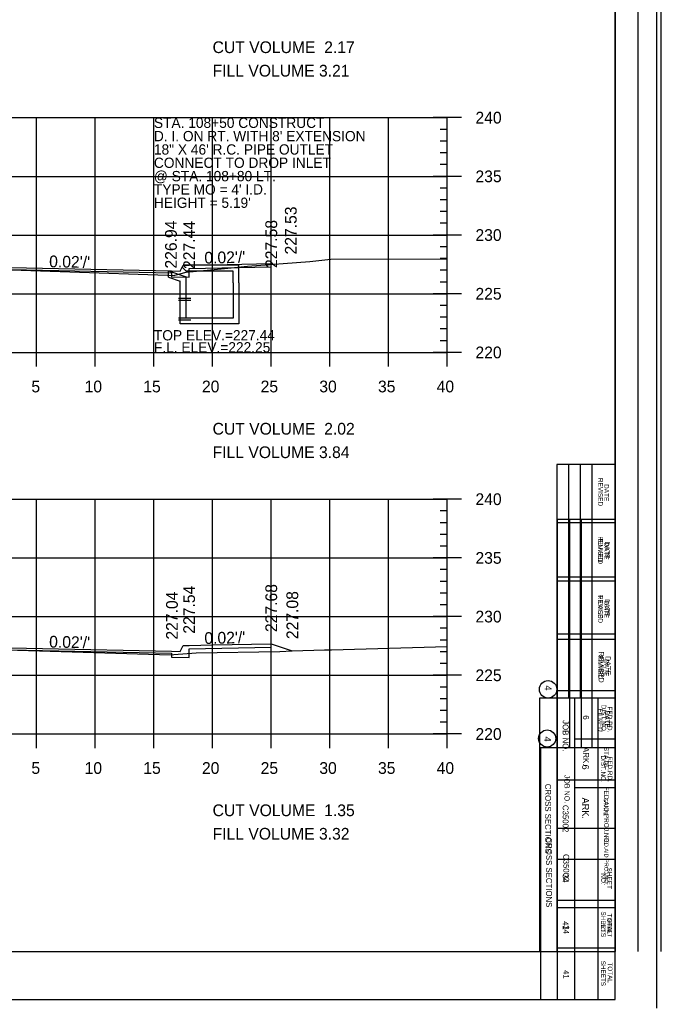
# Model space of a CAD drawing. Extents: x 1367903 to 1373764, y 376865 to 382130.
# Drawn here: x 1371989.4 to 1372098.7, y 377279.1 to 377447.5 of the extents above; entities that cross this region are included whole.
import ezdxf

# ---------------------------------------------------------------- set-up
doc = ezdxf.new("R2010")
doc.units = 0
for name, color, linetype in [('R_Axis', 7, 'Continuous'), ('R_Axis Annot', 7, 'Continuous'), ('R_Border', 7, 'Continuous'), ('R_Border Notes', 7, 'Continuous'), ('R_Border PE', 7, 'Continuous'), ('R_Draft', 7, 'Continuous'), ('R_Exist Surface', 7, 'Continuous'), ('R_Fin Surface', 7, 'Continuous'), ('R_Fin Surface Annot', 7, 'Continuous'), ('R_Grid', 7, 'Continuous'), ('R_Water', 7, 'Continuous'), ('R_Water Annot', 7, 'Continuous')]:
    doc.layers.add(name, color=color, linetype=linetype)

msp = doc.modelspace()

# ---------------------------------------------------------------- linework, layer by layer
for p, q in [((1372017.11, 377405.38), (1372017.28, 377405.71)), ((1372026.78, 377405.71), (1372017.28, 377405.71)), ((1372026.78, 377402.71), (1372026.78, 377405.71)), ((1372014.78, 377404.75), (1372017.78, 377403.71)), ((1372017.11, 377405.38), (1372017.78, 377404.71)), ((1372025.78, 377404.71), (1372017.78, 377404.71)), ((1372025.78, 377402.71), (1372025.78, 377404.71)), ((1372014.78, 377403.69), (1372016.78, 377403)), ((1372016.78, 377402.71), (1372016.78, 377403)), ((1372017.78, 377402.71), (1372017.78, 377403.71))]:
    msp.add_line(p, q)
for points in [[(1371946.28, 377405.71), (1371946.28, 377405.05), (1371946.28, 377405.05), (1371946.28, 377403.68), (1371949.28, 377403.74), (1371949.28, 377404.41), (1371982.28, 377405.07), (1372015.28, 377404.41), (1372015.28, 377403.74), (1372018.28, 377403.68), (1372018.28, 377405.13), (1372032.28, 377405.41), (1372032.28, 377405.99)], [(1372014.78, 377403.69), (1372014.78, 377404.75)], [(1371946.28, 377340.92), (1371946.28, 377340.25), (1371946.28, 377340.25), (1371946.28, 377338.89), (1371949.28, 377338.95), (1371949.28, 377339.62), (1371982.28, 377340.28), (1372015.28, 377339.62), (1372015.28, 377338.95), (1372018.28, 377338.89), (1372018.28, 377340.33), (1372032.28, 377340.61), (1372032.28, 377341.2)]]:
    msp.add_lwpolyline(points)
at = {"layer": 'R_Axis'}
for p, q in [((1372064.68, 377430.84), (1372059.88, 377430.84)), ((1372062.28, 377390.84), (1372062.28, 377430.84)), ((1372062.28, 377428.84), (1372061.08, 377428.84)), ((1372062.28, 377426.84), (1372061.08, 377426.84)), ((1372062.28, 377424.84), (1372061.08, 377424.84)), ((1372062.28, 377422.84), (1372061.08, 377422.84)), ((1372064.68, 377420.84), (1372059.88, 377420.84)), ((1372062.28, 377418.84), (1372061.08, 377418.84)), ((1372062.28, 377416.84), (1372061.08, 377416.84)), ((1372062.28, 377414.84), (1372061.08, 377414.84)), ((1372062.28, 377412.84), (1372061.08, 377412.84)), ((1372064.68, 377410.84), (1372059.88, 377410.84)), ((1372062.28, 377408.84), (1372061.08, 377408.84)), ((1372062.28, 377406.84), (1372061.08, 377406.84)), ((1372062.28, 377404.84), (1372061.08, 377404.84)), ((1372062.28, 377402.84), (1372061.08, 377402.84)), ((1372064.68, 377400.84), (1372059.88, 377400.84)), ((1372062.28, 377398.84), (1372061.08, 377398.84)), ((1372062.28, 377396.84), (1372061.08, 377396.84)), ((1372062.28, 377394.84), (1372061.08, 377394.84)), ((1371992.28, 377388.44), (1371992.28, 377393.24)), ((1372002.28, 377388.44), (1372002.28, 377393.24)), ((1372012.28, 377388.44), (1372012.28, 377393.24)), ((1372022.28, 377388.44), (1372022.28, 377393.24)), ((1372032.28, 377388.44), (1372032.28, 377393.24)), ((1372042.28, 377388.44), (1372042.28, 377393.24)), ((1372052.28, 377388.44), (1372052.28, 377393.24)), ((1372062.28, 377392.84), (1372061.08, 377392.84)), ((1372062.28, 377388.44), (1372062.28, 377393.24)), ((1371902.28, 377390.84), (1372062.28, 377390.84)), ((1372064.68, 377390.84), (1372059.88, 377390.84)), ((1372064.68, 377365.84), (1372059.88, 377365.84)), ((1372062.28, 377325.84), (1372062.28, 377365.84)), ((1372062.28, 377363.84), (1372061.08, 377363.84)), ((1372062.28, 377361.84), (1372061.08, 377361.84)), ((1372062.28, 377359.84), (1372061.08, 377359.84)), ((1372062.28, 377357.84), (1372061.08, 377357.84)), ((1372064.68, 377355.84), (1372059.88, 377355.84)), ((1372062.28, 377353.84), (1372061.08, 377353.84)), ((1372062.28, 377351.84), (1372061.08, 377351.84)), ((1372062.28, 377349.84), (1372061.08, 377349.84)), ((1372062.28, 377347.84), (1372061.08, 377347.84)), ((1372064.68, 377345.84), (1372059.88, 377345.84)), ((1372062.28, 377343.84), (1372061.08, 377343.84)), ((1372062.28, 377341.84), (1372061.08, 377341.84)), ((1372062.28, 377339.84), (1372061.08, 377339.84)), ((1372062.28, 377337.84), (1372061.08, 377337.84)), ((1372064.68, 377335.84), (1372059.88, 377335.84)), ((1372062.28, 377333.84), (1372061.08, 377333.84)), ((1372062.28, 377331.84), (1372061.08, 377331.84)), ((1372062.28, 377329.84), (1372061.08, 377329.84)), ((1371992.28, 377323.44), (1371992.28, 377328.24)), ((1372002.28, 377323.44), (1372002.28, 377328.24)), ((1372012.28, 377323.44), (1372012.28, 377328.24)), ((1372022.28, 377323.44), (1372022.28, 377328.24)), ((1372032.28, 377323.44), (1372032.28, 377328.24)), ((1372042.28, 377323.44), (1372042.28, 377328.24)), ((1372052.28, 377323.44), (1372052.28, 377328.24)), ((1372062.28, 377323.44), (1372062.28, 377328.24)), ((1372062.28, 377327.84), (1372061.08, 377327.84)), ((1371902.28, 377325.84), (1372062.28, 377325.84)), ((1372064.68, 377325.84), (1372059.88, 377325.84))]:
    msp.add_line(p, q, dxfattribs=at)
at = {"layer": 'R_Border'}
for p, q in [((1372097.94, 377620.35), (1372097.94, 377279.12)), ((1372090.9, 377280.59), (1372090.9, 377611.47)), ((1372090.9, 377446.03), (1372090.9, 377446.03)), ((1372081.09, 377280.59), (1372081.09, 377362.43)), ((1372081.09, 377362.43), (1372090.9, 377362.43)), ((1372081.09, 377362.43), (1372083.13, 377362.43)), ((1372083.13, 377362.43), (1372083.13, 377323.46)), ((1372085.07, 377362.43), (1372085.07, 377323.46)), ((1372086.92, 377362.43), (1372086.92, 377323.46)), ((1372081.09, 377352.62), (1372090.71, 377352.62)), ((1372081.09, 377342.9), (1372090.71, 377342.9)), ((1372081.09, 377333.27), (1372090.71, 377333.27)), ((1372090.9, 377323.46), (1372078.17, 377323.46)), ((1372078.17, 377323.46), (1372078.17, 377280.59)), ((1372084.01, 377280.59), (1372084.01, 377323.46)), ((1372087.99, 377280.59), (1372087.99, 377323.46)), ((1372090.9, 377316.65), (1372084.01, 377316.65)), ((1372090.9, 377309.75), (1372081.09, 377309.75)), ((1372090.9, 377296.24), (1372081.09, 377296.24)), ((1372090.9, 377289.33), (1372081.09, 377289.33)), ((1371886.58, 377280.59), (1372090.9, 377280.59))]:
    msp.add_line(p, q, dxfattribs=at)
msp.add_circle((1372079.31, 377325.07), 1.46, dxfattribs=at)
at = {"layer": 'R_Border PE'}
for p, q in [((1372094.83, 377288.8), (1372094.83, 377610.76)), ((1372098.74, 377288.8), (1372098.74, 377610.76)), ((1372090.9, 377603.25), (1372090.9, 377288.8)), ((1372080.96, 377371.74), (1372080.96, 377288.8)), ((1372090.9, 377371.74), (1372080.96, 377371.74)), ((1372082.95, 377371.74), (1372082.95, 377331.96)), ((1372084.93, 377371.74), (1372084.93, 377331.96)), ((1372086.92, 377371.74), (1372086.92, 377331.96)), ((1372090.9, 377361.8), (1372080.96, 377361.8)), ((1372090.9, 377351.85), (1372080.96, 377351.85)), ((1372090.9, 377341.91), (1372080.96, 377341.91)), ((1372090.9, 377331.96), (1372077.97, 377331.96)), ((1372077.97, 377331.96), (1372077.97, 377288.8)), ((1372083.94, 377331.96), (1372083.94, 377288.8)), ((1372087.92, 377331.96), (1372087.92, 377288.8)), ((1372084, 377325), (1372090.9, 377325)), ((1372081.09, 377318.04), (1372090.9, 377318.04)), ((1372081.09, 377304.51), (1372090.9, 377304.51)), ((1372081.09, 377297.55), (1372090.9, 377297.55)), ((1371886.58, 377288.8), (1372090.9, 377288.8)), ((1372088.01, 377288.8), (1372088.01, 377288.8))]:
    msp.add_line(p, q, dxfattribs=at)
msp.add_circle((1372079.46, 377333.45), 1.49, dxfattribs=at)
at = {"layer": 'R_Exist Surface'}
for points in [[(1371902.28, 377406.14), (1371906.78, 377405.89), (1371922.79, 377404.81), (1371925.98, 377404.62), (1371926.84, 377404.58), (1371935.66, 377404.33), (1371938.83, 377404.39), (1371949.02, 377404.45), (1371974.25, 377405), (1371981.24, 377405.14), (1372014.62, 377404), (1372015.78, 377403.97), (1372015.85, 377403.99), (1372017.8, 377404.51), (1372024.3, 377405.15), (1372028.24, 377405.56), (1372038.85, 377406.36), (1372042.42, 377406.71), (1372062.28, 377406.8)], [(1371902.28, 377342.31), (1371911.35, 377342.06), (1371922.67, 377340.92), (1371928.97, 377340.22), (1371929.76, 377340.14), (1371931.25, 377340.09), (1371937.71, 377339.83), (1371942.47, 377339.84), (1371949.84, 377339.76), (1371966.69, 377340.07), (1371981.54, 377340.33), (1372013.23, 377339.4), (1372015.37, 377339.34), (1372015.69, 377339.36), (1372019.46, 377339.64), (1372033.73, 377339.9), (1372035.84, 377340), (1372041.36, 377340.2), (1372042.57, 377340.19), (1372062.28, 377340.77)]]:
    msp.add_lwpolyline(points, dxfattribs=at)
at = {"layer": 'R_Fin Surface'}
for points in [[(1371942.37, 377404.41), (1371946.28, 377405.71), (1371947.28, 377405.71), (1371947.78, 377404.71), (1371949.28, 377404.74), (1371971.28, 377405.18), (1371982.28, 377405.4), (1371993.28, 377405.18), (1372015.28, 377404.74), (1372016.78, 377404.71), (1372017.28, 377405.71), (1372018.28, 377405.71), (1372022.28, 377405.79), (1372032.28, 377405.99), (1372032.58, 377405.89)], [(1371943.02, 377339.83), (1371946.28, 377340.92), (1371947.28, 377340.92), (1371947.78, 377339.92), (1371949.28, 377339.95), (1371971.28, 377340.39), (1371982.28, 377340.61), (1371993.28, 377340.39), (1372015.28, 377339.95), (1372016.78, 377339.92), (1372017.28, 377340.92), (1372018.28, 377340.92), (1372022.28, 377341), (1372032.28, 377341.2), (1372035.87, 377340)]]:
    msp.add_lwpolyline(points, dxfattribs=at)
at = {"layer": 'R_Grid'}
for p, q in [((1371902.28, 377430.84), (1372062.28, 377430.84)), ((1371992.28, 377390.84), (1371992.28, 377430.84)), ((1372002.28, 377390.84), (1372002.28, 377430.84)), ((1372012.28, 377390.84), (1372012.28, 377430.84)), ((1372022.28, 377390.84), (1372022.28, 377430.84)), ((1372032.28, 377390.84), (1372032.28, 377430.84)), ((1372042.28, 377390.84), (1372042.28, 377430.84)), ((1372052.28, 377390.84), (1372052.28, 377430.84)), ((1372062.28, 377390.84), (1372062.28, 377430.84)), ((1371902.28, 377420.84), (1372062.28, 377420.84)), ((1371902.28, 377410.84), (1372062.28, 377410.84)), ((1371902.28, 377400.84), (1372062.28, 377400.84)), ((1371902.28, 377390.84), (1372062.28, 377390.84)), ((1371902.28, 377365.84), (1372062.28, 377365.84)), ((1371992.28, 377325.84), (1371992.28, 377365.84)), ((1372002.28, 377325.84), (1372002.28, 377365.84)), ((1372012.28, 377325.84), (1372012.28, 377365.84)), ((1372022.28, 377325.84), (1372022.28, 377365.84)), ((1372032.28, 377325.84), (1372032.28, 377365.84)), ((1372042.28, 377325.84), (1372042.28, 377365.84)), ((1372052.28, 377325.84), (1372052.28, 377365.84)), ((1372062.28, 377325.84), (1372062.28, 377365.84)), ((1371902.28, 377355.84), (1372062.28, 377355.84)), ((1371902.28, 377345.84), (1372062.28, 377345.84)), ((1371902.28, 377335.84), (1372062.28, 377335.84)), ((1371902.28, 377325.84), (1372062.28, 377325.84))]:
    msp.add_line(p, q, dxfattribs=at)
at = {"layer": 'R_Water'}
for p, q in [((1372018.59, 377400.02), (1372016.49, 377400.01)), ((1372018.59, 377399.69), (1372016.49, 377399.67)), ((1372018.59, 377396.69), (1372016.49, 377396.67)), ((1372018.59, 377396.36), (1372016.49, 377396.34))]:
    msp.add_line(p, q, dxfattribs=at)
for points in [[(1372026.78, 377402.71), (1372026.78, 377395.69), (1372021.78, 377395.69), (1372016.78, 377395.69), (1372016.78, 377402.71)], [(1372025.78, 377402.71), (1372025.78, 377396.69), (1372021.78, 377396.69), (1372017.78, 377396.69), (1372017.78, 377402.71)]]:
    msp.add_lwpolyline(points, dxfattribs=at)

# ---------------------------------------------------------------- texts
at = {"layer": 'R_Axis Annot'}
for s, p in [('CUT VOLUME  2.17', (1372022.28, 377441.84)), ('FILL VOLUME 3.21', (1372022.28, 377437.84)), ('240', (1372067.08, 377429.84)), ('235', (1372067.08, 377419.84)), ('230', (1372067.08, 377409.84)), ('225', (1372067.08, 377399.84)), ('220', (1372067.08, 377389.84)), ('5', (1371991.4, 377384.04)), ('10', (1372000.47, 377384.04)), ('15', (1372010.47, 377384.04)), ('20', (1372020.47, 377384.04)), ('25', (1372030.47, 377384.04)), ('30', (1372040.47, 377384.04)), ('35', (1372050.47, 377384.04)), ('40', (1372060.47, 377384.04)), ('CUT VOLUME  2.02', (1372022.28, 377376.84)), ('FILL VOLUME 3.84', (1372022.28, 377372.84)), ('240', (1372067.08, 377364.84)), ('235', (1372067.08, 377354.84)), ('230', (1372067.08, 377344.84)), ('225', (1372067.08, 377334.84)), ('220', (1372067.08, 377324.84)), ('5', (1371991.4, 377319.04)), ('10', (1372000.47, 377319.04)), ('15', (1372010.47, 377319.04)), ('20', (1372020.47, 377319.04)), ('25', (1372030.47, 377319.04)), ('30', (1372040.47, 377319.04)), ('35', (1372050.47, 377319.04)), ('40', (1372060.47, 377319.04)), ('CUT VOLUME  1.35', (1372022.28, 377311.84)), ('FILL VOLUME 3.32', (1372022.28, 377307.84))]:
    msp.add_text(s, height=2, dxfattribs=at).set_placement(p)
at = {"layer": 'R_Border'}
for s, height, p in [('REVISED', 0.778, (1372087.99, 377359.51)), ('DATE', 0.778, (1372089.15, 377358.64)), ('FILMED', 0.778, (1372087.99, 377349.41)), ('DATE', 0.778, (1372089.15, 377348.82)), ('REVISED', 0.875, (1372088.09, 377339.88)), ('DATE', 0.875, (1372089.25, 377339.1)), ('FILMED', 0.778, (1372087.99, 377330.16)), ('DATE', 0.778, (1372089.15, 377329.77)), ('4', 1.17, (1372078.8, 377325.4)), ('DIST.NO.', 0.778, (1372088.48, 377322.19)), ('FED.RD.', 0.778, (1372089.64, 377321.99)), ('6', 1.17, (1372085.26, 377320.63)), ('JOB NO.', 0.875, (1372082.26, 377318.88)), ('ARK.', 1.166, (1372085.26, 377315)), ('STATE', 0.681, (1372088.96, 377314.9)), ('FED.AID PROJ.NO.', 0.6805, (1372089.06, 377308.49)), ('NO.', 0.681, (1372088.48, 377293.61)), ('SHEET', 0.681, (1372089.64, 377294.39)), ('SHEETS', 0.778, (1372088.48, 377287.2)), ('TOTAL', 0.778, (1372089.64, 377286.91))]:
    msp.add_text(s, height=height, rotation=270, dxfattribs=at).set_placement(p)
at = {"layer": 'R_Border Notes'}
for s, height, p in [('CROSS SECTIONS', 0.9945, (1372079.13, 377308.2)), ('C35002', 0.995, (1372082.05, 377305.39)), ('34', 0.995, (1372082.05, 377293.25)), ('41', 0.995, (1372082.05, 377285.62))]:
    msp.add_text(s, height=height, rotation=270, dxfattribs=at).set_placement(p)
at = {"layer": 'R_Border PE'}
for s, height, p in [('REVISED', 0.796, (1372088, 377369.47)), ('DATE', 0.796, (1372089.03, 377368.41)), ('FILMED', 0.796, (1372088, 377359.12)), ('DATE', 0.796, (1372089.03, 377358.47)), ('REVISED', 0.796, (1372088, 377349.57)), ('DATE', 0.796, (1372089.03, 377348.52)), ('FILMED', 0.796, (1372088, 377339.23)), ('DATE', 0.796, (1372089.03, 377338.58)), ('4', 1.19, (1372078.87, 377334.12)), ('DIST.NO.', 0.796, (1372088.57, 377330.83)), ('FED.RD.', 0.796, (1372089.6, 377330.52)), ('JOB NO.', 0.995, (1372081.95, 377328.19)), ('6', 0.995, (1372085.43, 377329.02)), ('ARK.', 0.995, (1372085.43, 377323.6)), ('STATE', 0.796, (1372089.01, 377323.66)), ('CROSS SECTIONS', 0.9945, (1372078.97, 377317.35)), ('FED.AID PROJ.NO.', 0.7956, (1372089.01, 377316.88)), ('C35002', 0.995, (1372081.95, 377313.75)), ('SHEET', 0.796, (1372089.53, 377303.09)), ('34', 0.995, (1372081.95, 377301.98)), ('NO.', 0.796, (1372088.5, 377302.11)), ('SHEETS', 0.796, (1372088.5, 377295.62)), ('TOTAL', 0.796, (1372089.53, 377295.23)), ('41', 0.995, (1372081.95, 377293.96))]:
    msp.add_text(s, height=height, rotation=270, dxfattribs=at).set_placement(p)
at = {"layer": 'R_Draft'}
for s, p in [('STA. 108+50 CONSTRUCT', (1372012.28, 377429.09)), ("D. I. ON RT. WITH 8' EXTENSION", (1372012.28, 377426.82)), ('18" X 46\' R.C. PIPE OUTLET', (1372012.28, 377424.55)), ('CONNECT TO DROP INLET', (1372012.28, 377422.28)), ('@ STA. 108+80 LT.', (1372012.28, 377420.01)), ("TYPE MO = 4' I.D.", (1372012.28, 377417.74)), ("HEIGHT = 5.19'", (1372012.28, 377415.47))]:
    msp.add_text(s, height=1.75, dxfattribs=at).set_placement(p)
at = {"layer": 'R_Fin Surface Annot'}
for s, rotation, p in [('227.53', 90, (1372036.61, 377407.53)), ('226.94', 90, (1372016.18, 377405.13)), ('227.44', 90, (1372019.28, 377405.06)), ('227.58', 90, (1372033.28, 377405.23)), ("0.02'/'", 358.8542, (1371994.41, 377405.36)), ("0.02'/'", 1.1458, (1372020.9, 377405.97)), ('227.04', 90, (1372016.35, 377341.92)), ('227.54', 90, (1372019.28, 377342.92)), ('227.68', 90, (1372033.28, 377343.2)), ('227.08', 90, (1372036.87, 377342)), ("0.02'/'", 1.1458, (1372020.9, 377341.17)), ("0.02'/'", 358.8542, (1371994.41, 377340.57))]:
    msp.add_text(s, height=2, rotation=rotation, dxfattribs=at).set_placement(p)
at = {"layer": 'R_Water Annot'}
for s, p in [('TOP ELEV.=227.44', (1372012.28, 377392.89)), ('F.L. ELEV.=222.25', (1372012.28, 377390.84))]:
    msp.add_text(s, height=1.75, dxfattribs=at).set_placement(p)

doc.saveas('drawing.dxf')
